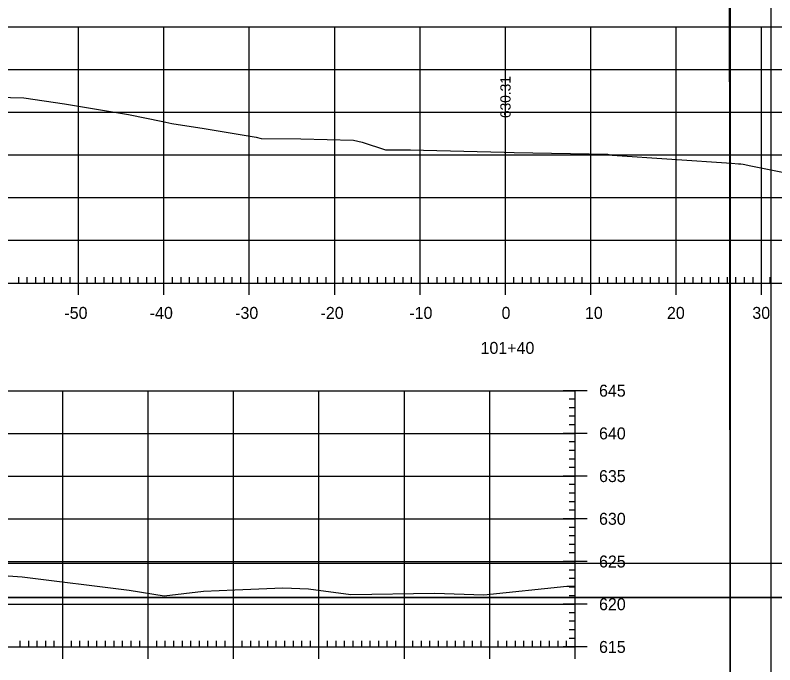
# Model space of a CAD drawing. Extents: x 1381471 to 1382703, y 370300 to 371487.
# Drawn here: x 1382079.2 to 1382168.2, y 370412.6 to 370488.6 of the extents above; entities that cross this region are included whole.
import ezdxf

# ---------------------------------------------------------------- set-up
doc = ezdxf.new("R2010")
doc.units = 0
for name, color, linetype in [('Level 18', 7, 'Continuous'), ('Level 22', 7, 'Continuous'), ('Level 26', 7, 'Continuous'), ('Level 4', 7, 'Continuous'), ('Level 45', 7, 'Continuous'), ('Level 5', 7, 'Continuous'), ('Level 6', 7, 'Continuous')]:
    doc.layers.add(name, color=color, linetype=linetype)

msp = doc.modelspace()

# ---------------------------------------------------------------- linework, layer by layer
at = {"layer": 'Level 18'}
msp.add_lwpolyline([(1382065.759, 370423.896), (1382080.002, 370422.866), (1382092.546, 370421.319), (1382096.626, 370420.639), (1382101.247, 370421.211), (1382104.923, 370421.354), (1382110.554, 370421.572), (1382113.562, 370421.465), (1382118.493, 370420.818), (1382128.319, 370420.955), (1382134.084, 370420.749), (1382143.812, 370421.775), (1382144.772, 370421.777)], dxfattribs=at)
at = {"layer": 'Level 22'}
for p, q in [((1381864.772, 370444.662), (1382144.772, 370444.662)), ((1382084.772, 370414.662), (1382084.772, 370444.662)), ((1382094.772, 370414.662), (1382094.772, 370444.662)), ((1382104.772, 370414.662), (1382104.772, 370444.662)), ((1382114.772, 370414.662), (1382114.772, 370444.662)), ((1382124.772, 370414.662), (1382124.772, 370444.662)), ((1382134.772, 370414.662), (1382134.772, 370444.662)), ((1382144.772, 370414.662), (1382144.772, 370444.662)), ((1381864.772, 370439.662), (1382144.772, 370439.662)), ((1381864.772, 370434.662), (1382144.772, 370434.662)), ((1381864.772, 370429.662), (1382144.772, 370429.662)), ((1381864.772, 370424.662), (1382144.772, 370424.662)), ((1381864.772, 370419.662), (1382144.772, 370419.662)), ((1381864.772, 370414.662), (1382144.772, 370414.662))]:
    msp.add_line(p, q, dxfattribs=at)
at = {"layer": 'Level 26'}
for points in [[(1381834.365, 370547.628), (1382167.705, 370547.628), (1382167.705, 370334.29), (1381834.365, 370334.29)], [(1382080.692, 370543.733), (1382100.312, 370543.733), (1382100.312, 370533.853), (1382116.424, 370533.853), (1382139.624, 370533.853), (1382139.624, 370501.183), (1382162.831, 370501.183), (1382162.952, 370338.273), (1381846.772, 370338.273), (1381846.772, 370543.733)]]:
    msp.add_lwpolyline(points, close=True, dxfattribs=at)
at = {"layer": 'Level 4'}
for p, q in [((1382146.172, 370444.662), (1382143.372, 370444.662)), ((1382144.772, 370414.662), (1382144.772, 370444.662)), ((1382144.772, 370443.662), (1382144.072, 370443.662)), ((1382144.772, 370442.662), (1382144.072, 370442.662)), ((1382144.772, 370441.662), (1382144.072, 370441.662)), ((1382144.772, 370440.662), (1382144.072, 370440.662)), ((1382146.172, 370439.662), (1382143.372, 370439.662)), ((1382144.772, 370438.662), (1382144.072, 370438.662)), ((1382144.772, 370437.662), (1382144.072, 370437.662)), ((1382144.772, 370436.662), (1382144.072, 370436.662)), ((1382144.772, 370435.662), (1382144.072, 370435.662)), ((1382146.172, 370434.662), (1382143.372, 370434.662)), ((1382144.772, 370433.662), (1382144.072, 370433.662)), ((1382144.772, 370432.662), (1382144.072, 370432.662)), ((1382144.772, 370431.662), (1382144.072, 370431.662)), ((1382144.772, 370430.662), (1382144.072, 370430.662)), ((1382146.172, 370429.662), (1382143.372, 370429.662)), ((1382144.772, 370428.662), (1382144.072, 370428.662)), ((1382144.772, 370427.662), (1382144.072, 370427.662)), ((1382144.772, 370426.662), (1382144.072, 370426.662)), ((1382144.772, 370425.662), (1382144.072, 370425.662)), ((1382146.172, 370424.662), (1382143.372, 370424.662)), ((1382144.772, 370423.662), (1382144.072, 370423.662)), ((1382144.772, 370422.662), (1382144.072, 370422.662)), ((1382144.772, 370421.662), (1382144.072, 370421.662)), ((1382144.772, 370420.662), (1382144.072, 370420.662)), ((1382146.172, 370419.662), (1382143.372, 370419.662)), ((1382144.772, 370418.662), (1382144.072, 370418.662)), ((1382144.772, 370417.662), (1382144.072, 370417.662)), ((1382144.772, 370416.662), (1382144.072, 370416.662)), ((1382084.772, 370413.262), (1382084.772, 370416.062)), ((1382094.772, 370413.262), (1382094.772, 370416.062)), ((1382104.772, 370413.262), (1382104.772, 370416.062)), ((1382114.772, 370413.262), (1382114.772, 370416.062)), ((1382124.772, 370413.262), (1382124.772, 370416.062)), ((1382134.772, 370413.262), (1382134.772, 370416.062)), ((1382144.772, 370415.662), (1382144.072, 370415.662)), ((1382144.772, 370413.262), (1382144.772, 370416.062)), ((1381864.772, 370414.662), (1382144.772, 370414.662)), ((1382079.772, 370414.662), (1382079.772, 370415.362)), ((1382080.772, 370414.662), (1382080.772, 370415.362)), ((1382081.772, 370414.662), (1382081.772, 370415.362)), ((1382082.772, 370414.662), (1382082.772, 370415.362)), ((1382083.772, 370414.662), (1382083.772, 370415.362)), ((1382085.772, 370414.662), (1382085.772, 370415.362)), ((1382086.772, 370414.662), (1382086.772, 370415.362)), ((1382087.772, 370414.662), (1382087.772, 370415.362)), ((1382088.772, 370414.662), (1382088.772, 370415.362)), ((1382089.772, 370414.662), (1382089.772, 370415.362)), ((1382090.772, 370414.662), (1382090.772, 370415.362)), ((1382091.772, 370414.662), (1382091.772, 370415.362)), ((1382092.772, 370414.662), (1382092.772, 370415.362)), ((1382093.772, 370414.662), (1382093.772, 370415.362)), ((1382095.772, 370414.662), (1382095.772, 370415.362)), ((1382096.772, 370414.662), (1382096.772, 370415.362)), ((1382097.772, 370414.662), (1382097.772, 370415.362)), ((1382098.772, 370414.662), (1382098.772, 370415.362)), ((1382099.772, 370414.662), (1382099.772, 370415.362)), ((1382100.772, 370414.662), (1382100.772, 370415.362)), ((1382101.772, 370414.662), (1382101.772, 370415.362)), ((1382102.772, 370414.662), (1382102.772, 370415.362)), ((1382103.772, 370414.662), (1382103.772, 370415.362)), ((1382105.772, 370414.662), (1382105.772, 370415.362)), ((1382106.772, 370414.662), (1382106.772, 370415.362)), ((1382107.772, 370414.662), (1382107.772, 370415.362)), ((1382108.772, 370414.662), (1382108.772, 370415.362)), ((1382109.772, 370414.662), (1382109.772, 370415.362)), ((1382110.772, 370414.662), (1382110.772, 370415.362)), ((1382111.772, 370414.662), (1382111.772, 370415.362)), ((1382112.772, 370414.662), (1382112.772, 370415.362)), ((1382113.772, 370414.662), (1382113.772, 370415.362)), ((1382115.772, 370414.662), (1382115.772, 370415.362)), ((1382116.772, 370414.662), (1382116.772, 370415.362)), ((1382117.772, 370414.662), (1382117.772, 370415.362)), ((1382118.772, 370414.662), (1382118.772, 370415.362)), ((1382119.772, 370414.662), (1382119.772, 370415.362)), ((1382120.772, 370414.662), (1382120.772, 370415.362)), ((1382121.772, 370414.662), (1382121.772, 370415.362)), ((1382122.772, 370414.662), (1382122.772, 370415.362)), ((1382123.772, 370414.662), (1382123.772, 370415.362)), ((1382125.772, 370414.662), (1382125.772, 370415.362)), ((1382126.772, 370414.662), (1382126.772, 370415.362)), ((1382127.772, 370414.662), (1382127.772, 370415.362)), ((1382128.772, 370414.662), (1382128.772, 370415.362)), ((1382129.772, 370414.662), (1382129.772, 370415.362)), ((1382130.772, 370414.662), (1382130.772, 370415.362)), ((1382131.772, 370414.662), (1382131.772, 370415.362)), ((1382132.772, 370414.662), (1382132.772, 370415.362)), ((1382133.772, 370414.662), (1382133.772, 370415.362)), ((1382135.772, 370414.662), (1382135.772, 370415.362)), ((1382136.772, 370414.662), (1382136.772, 370415.362)), ((1382137.772, 370414.662), (1382137.772, 370415.362)), ((1382138.772, 370414.662), (1382138.772, 370415.362)), ((1382139.772, 370414.662), (1382139.772, 370415.362)), ((1382140.772, 370414.662), (1382140.772, 370415.362)), ((1382141.772, 370414.662), (1382141.772, 370415.362)), ((1382142.772, 370414.662), (1382142.772, 370415.362)), ((1382146.172, 370414.662), (1382143.372, 370414.662)), ((1382143.772, 370414.662), (1382143.772, 370415.362))]:
    msp.add_line(p, q, dxfattribs=at)
at = {"layer": 'Level 45'}
for p, q in [((1381996.613, 370487.267), (1382276.613, 370487.267)), ((1382086.613, 370457.267), (1382086.613, 370487.267)), ((1382096.613, 370457.267), (1382096.613, 370487.267)), ((1382106.613, 370457.267), (1382106.613, 370487.267)), ((1382116.613, 370457.267), (1382116.613, 370487.267)), ((1382126.613, 370457.267), (1382126.613, 370487.267)), ((1382136.613, 370457.267), (1382136.613, 370487.267)), ((1382146.613, 370457.267), (1382146.613, 370487.267)), ((1382156.613, 370457.267), (1382156.613, 370487.267)), ((1382166.613, 370457.267), (1382166.613, 370487.267)), ((1381996.613, 370482.267), (1382276.613, 370482.267)), ((1381996.613, 370477.267), (1382276.613, 370477.267)), ((1381996.613, 370472.267), (1382276.613, 370472.267)), ((1381996.613, 370467.267), (1382276.613, 370467.267)), ((1381996.613, 370462.267), (1382276.613, 370462.267)), ((1382086.613, 370455.867), (1382086.613, 370458.667)), ((1382096.613, 370455.867), (1382096.613, 370458.667)), ((1382106.613, 370455.867), (1382106.613, 370458.667)), ((1382116.613, 370455.867), (1382116.613, 370458.667)), ((1382126.613, 370455.867), (1382126.613, 370458.667)), ((1382136.613, 370455.867), (1382136.613, 370458.667)), ((1382146.613, 370455.867), (1382146.613, 370458.667)), ((1382156.613, 370455.867), (1382156.613, 370458.667)), ((1382166.613, 370455.867), (1382166.613, 370458.667)), ((1382079.613, 370457.267), (1382079.613, 370457.967)), ((1382080.613, 370457.267), (1382080.613, 370457.967)), ((1382081.613, 370457.267), (1382081.613, 370457.967)), ((1382082.613, 370457.267), (1382082.613, 370457.967)), ((1382083.613, 370457.267), (1382083.613, 370457.967)), ((1382084.613, 370457.267), (1382084.613, 370457.967)), ((1382085.613, 370457.267), (1382085.613, 370457.967)), ((1382087.613, 370457.267), (1382087.613, 370457.967)), ((1382088.613, 370457.267), (1382088.613, 370457.967)), ((1382089.613, 370457.267), (1382089.613, 370457.967)), ((1382090.613, 370457.267), (1382090.613, 370457.967)), ((1382091.613, 370457.267), (1382091.613, 370457.967)), ((1382092.613, 370457.267), (1382092.613, 370457.967)), ((1382093.613, 370457.267), (1382093.613, 370457.967)), ((1382094.613, 370457.267), (1382094.613, 370457.967)), ((1382095.613, 370457.267), (1382095.613, 370457.967)), ((1382097.613, 370457.267), (1382097.613, 370457.967)), ((1382098.613, 370457.267), (1382098.613, 370457.967)), ((1382099.613, 370457.267), (1382099.613, 370457.967)), ((1382100.613, 370457.267), (1382100.613, 370457.967)), ((1382101.613, 370457.267), (1382101.613, 370457.967)), ((1382102.613, 370457.267), (1382102.613, 370457.967)), ((1382103.613, 370457.267), (1382103.613, 370457.967)), ((1382104.613, 370457.267), (1382104.613, 370457.967)), ((1382105.613, 370457.267), (1382105.613, 370457.967)), ((1382107.613, 370457.267), (1382107.613, 370457.967)), ((1382108.613, 370457.267), (1382108.613, 370457.967)), ((1382109.613, 370457.267), (1382109.613, 370457.967)), ((1382110.613, 370457.267), (1382110.613, 370457.967)), ((1382111.613, 370457.267), (1382111.613, 370457.967)), ((1382112.613, 370457.267), (1382112.613, 370457.967)), ((1382113.613, 370457.267), (1382113.613, 370457.967)), ((1382114.613, 370457.267), (1382114.613, 370457.967)), ((1382115.613, 370457.267), (1382115.613, 370457.967)), ((1382117.613, 370457.267), (1382117.613, 370457.967)), ((1382118.613, 370457.267), (1382118.613, 370457.967)), ((1382119.613, 370457.267), (1382119.613, 370457.967)), ((1382120.613, 370457.267), (1382120.613, 370457.967)), ((1382121.613, 370457.267), (1382121.613, 370457.967)), ((1382122.613, 370457.267), (1382122.613, 370457.967)), ((1382123.613, 370457.267), (1382123.613, 370457.967)), ((1382124.613, 370457.267), (1382124.613, 370457.967)), ((1382125.613, 370457.267), (1382125.613, 370457.967)), ((1382127.613, 370457.267), (1382127.613, 370457.967)), ((1382128.613, 370457.267), (1382128.613, 370457.967)), ((1382129.613, 370457.267), (1382129.613, 370457.967)), ((1382130.613, 370457.267), (1382130.613, 370457.967)), ((1382131.613, 370457.267), (1382131.613, 370457.967)), ((1382132.613, 370457.267), (1382132.613, 370457.967)), ((1382133.613, 370457.267), (1382133.613, 370457.967)), ((1382134.613, 370457.267), (1382134.613, 370457.967)), ((1382135.613, 370457.267), (1382135.613, 370457.967)), ((1382137.613, 370457.267), (1382137.613, 370457.967)), ((1382138.613, 370457.267), (1382138.613, 370457.967)), ((1382139.613, 370457.267), (1382139.613, 370457.967)), ((1382140.613, 370457.267), (1382140.613, 370457.967)), ((1382141.613, 370457.267), (1382141.613, 370457.967)), ((1382142.613, 370457.267), (1382142.613, 370457.967)), ((1382143.613, 370457.267), (1382143.613, 370457.967)), ((1382144.613, 370457.267), (1382144.613, 370457.967)), ((1382145.613, 370457.267), (1382145.613, 370457.967)), ((1382147.613, 370457.267), (1382147.613, 370457.967)), ((1382148.613, 370457.267), (1382148.613, 370457.967)), ((1382149.613, 370457.267), (1382149.613, 370457.967)), ((1382150.613, 370457.267), (1382150.613, 370457.967)), ((1382151.613, 370457.267), (1382151.613, 370457.967)), ((1382152.613, 370457.267), (1382152.613, 370457.967)), ((1382153.613, 370457.267), (1382153.613, 370457.967)), ((1382154.613, 370457.267), (1382154.613, 370457.967)), ((1382155.613, 370457.267), (1382155.613, 370457.967)), ((1382157.613, 370457.267), (1382157.613, 370457.967)), ((1382158.613, 370457.267), (1382158.613, 370457.967)), ((1382159.613, 370457.267), (1382159.613, 370457.967)), ((1382160.613, 370457.267), (1382160.613, 370457.967)), ((1382161.613, 370457.267), (1382161.613, 370457.967)), ((1382162.613, 370457.267), (1382162.613, 370457.967)), ((1382163.613, 370457.267), (1382163.613, 370457.967)), ((1382164.613, 370457.267), (1382164.613, 370457.967)), ((1382165.613, 370457.267), (1382165.613, 370457.967)), ((1382167.613, 370457.267), (1382167.613, 370457.967)), ((1381996.613, 370457.267), (1382276.613, 370457.267)), ((1381996.613, 370457.267), (1382276.613, 370457.267)), ((1382294.793, 370424.444), (1381978.613, 370424.444)), ((1381966.213, 370420.466), (1382299.546, 370420.466))]:
    msp.add_line(p, q, dxfattribs=at)
for points in [[(1381966.206, 370633.799), (1382299.546, 370633.799), (1382299.546, 370420.461), (1381966.206, 370420.461)], [(1382212.533, 370629.904), (1382232.153, 370629.904), (1382232.153, 370620.024), (1382248.266, 370620.024), (1382271.465, 370620.024), (1382271.465, 370595.692), (1382294.793, 370595.692), (1382294.793, 370424.444), (1381978.613, 370424.444), (1381978.613, 370629.904)]]:
    msp.add_lwpolyline(points, close=True, dxfattribs=at)
msp.add_lwpolyline([(1382075.49, 370479.07), (1382080.203, 370478.929), (1382084.956, 370478.257), (1382092.455, 370476.997), (1382096.473, 370476.163), (1382097.528, 370475.945), (1382101.336, 370475.363), (1382107.403, 370474.356), (1382108.018, 370474.18), (1382112.637, 370474.162), (1382118.823, 370474.001), (1382119.836, 370473.761), (1382122.559, 370472.853), (1382125.3, 370472.845), (1382125.474, 370472.848), (1382127.025, 370472.81), (1382136.456, 370472.574), (1382137.635, 370472.553), (1382148.604, 370472.362), (1382149.128, 370472.245), (1382163.089, 370471.29), (1382163.895, 370471.232), (1382164.024, 370471.223), (1382164.085, 370471.219), (1382164.17, 370471.213), (1382164.448, 370471.188), (1382165.335, 370470.97), (1382178.793, 370468.309)], dxfattribs=at)
at = {"layer": 'Level 6'}
msp.add_line((1382162.952, 370338.273), (1382162.952, 370543.733), dxfattribs=at)

# ---------------------------------------------------------------- texts
at = {"layer": 'Level 45'}
msp.add_text('630.31', height=1.2, rotation=90, dxfattribs=at).set_placement((1382137.213, 370476.577))
for s, p in [('-50', (1382084.954, 370453.067)), ('-40', (1382094.954, 370453.067)), ('-30', (1382104.954, 370453.067)), ('-20', (1382114.954, 370453.067)), ('-10', (1382125.351, 370453.067)), ('0', (1382136.156, 370453.067)), ('10', (1382145.924, 370453.067)), ('20', (1382155.528, 370453.067)), ('30', (1382165.528, 370453.067)), ('101+40', (1382133.698, 370448.967))]:
    msp.add_text(s, height=1.4, dxfattribs=at).set_placement(p)
at = {"layer": 'Level 5'}
for s, p in [('645', (1382147.572, 370443.962)), ('640', (1382147.572, 370438.962)), ('635', (1382147.572, 370433.962)), ('630', (1382147.572, 370428.962)), ('625', (1382147.572, 370423.962)), ('620', (1382147.572, 370418.962)), ('615', (1382147.572, 370413.962))]:
    msp.add_text(s, height=1.4, dxfattribs=at).set_placement(p)

doc.saveas('drawing.dxf')
